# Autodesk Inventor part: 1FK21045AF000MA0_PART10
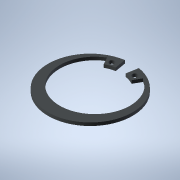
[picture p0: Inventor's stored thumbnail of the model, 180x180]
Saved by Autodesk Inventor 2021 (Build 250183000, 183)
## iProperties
Created: 2025-04
Part Number: 1FK21045AF000MA0_PART10
Material: Generic
Catalog Web Link: www.3dfindit.com
Description: -Servo synchronous motor
Document SubType Name: Modeling
Designer: psAdmin
Mass: 0.642463 g
Surface Area: 12.3927 cm^2
Volume: 0.642463 cm^3
Density: 1 g/cm^3
Appearance: PSOLRGB-212-217-219
Category: PARTsolutions
Title: 1FK21045AF000MA0_PART10
Author: Cadenas PARTsolutions
Comments: Servo synchronous motor
Sending System: PARTsolutions
Preprocessor: ST-DEVELOPER v19.3
PSOL_IDENT_0: {$CADENAS_DATA/23d-libs/siemens_ag/_cat_/8b/0a/1fk21045af000ma0.prj},216 {VTYP=3D},{NB=1FK21045AF000
PSOL_IDENT_1: MA0_PART10},{LINA=1FK21045AF000MA0_PART10},{NN=1FK21045AF000MA0_PART10},{NOPRJ=TRUE},{DATE=19.08.202
PSOL_IDENT_2: 5 14:00:48},{GEOMDATE=30.07.2025 02:00:28},{VERSION=},{LINEID=10},{WBVAR=},{WBNUMERIC=}  {NB=1FK2104
PSOL_IDENT_3: 5AF000MA0_PART10},{LINA=1FK21045AF000MA0_PART10},{KT=DUMMY},{PREVIEW=../../../_pool_/a9/69/p_d211_xx
PSOL_IDENT_4: _00818j.png},{DESCSHORT=SIMOTICS S-1FK2 HD, SINAMICS S210 3AC 400V-480V, 2.4 Nm, 3000 rpm},{DESCLONG=
PSOL_IDENT_5: SIMOTICS S-1FK2 HD servo motor M0=2.4 Nm; PN = 0.75 kW at nN=3000 rpm (380-480 V); PN = 0.375 kW at
PSOL_IDENT_6: nN=1500 rpm (200-240 V); degree of protection IP64; cylindrical shaft D19x40mm; absolute encoder 22-
PSOL_IDENT_7: bit + 12-bit multiturn (encoder AM22DQC); with OCC interface; plug size M17, rotatable; SIMOTICS S-1
PSOL_IDENT_8: FK2 servomotorfor a wide range of uses in industrial environments. SIMOTICS S‑1FK2 servomotors are c
PSOL_IDENT_9: ompact synchronous motors with a high dynamic performance that set themselves apart as a result of t
PSOL_IDENT_10: heir high power density, degree of protection and overload capability. The motors are available in t
PSOL_IDENT_11: wo variants: as High Dynamic variant (highest dynamic performance as a result of the low intrinsic m
PSOL_IDENT_12: oment of inertia for applications demanding a high dynamic performance with low moved masses) - and
PSOL_IDENT_13: as Compact variant (precise and stable closed-loop control for medium up to large moved masses as a
PSOL_IDENT_14: result of a medium intrinsic moment of inertia). SIMOTICSS‑1FK2 servomotors fully exploit their stre
PSOL_IDENT_15: ngths in a system with the SINAMICSS210 frequency converter and simple connection using the one cabl
PSOL_IDENT_16: e connection (OCC). Advantages include the short control and positioning times, fast and precise cor
PSOL_IDENT_17: rection of disturbing quantities as well as stable control with a high dynamic performance. The serv
PSOL_IDENT_18: o motors can be configured to address a wide range of requirements. For example with and without hol
PSOL_IDENT_19: ding brake, IP64 or IP65 degree of protection, singleturn or multiturn absolute encoders - to name j
PSOL_IDENT_20: ust a few. Further, the servomotors are available in different shaft heights extending from 20 to 10
PSOL_IDENT_21: 0. A shaft sealing ring is available to achieve an IP65 degree of protection and for subsequent moun
PSOL_IDENT_22: ting at the motor or as spare part. SIMOTICS - the optimum motor for each and every motion control a
PSOL_IDENT_23: pplication.},{INTNO=195125050112},{SUPPLIERALTNO=1FK2104-5AF00-0MA0},{MANUID=1FK21045AF000MA0},{MANU
PSOL_IDENT_24: NAME=Siemens},{MANUTYPEDESC=Synchronous motor 1FK2-HD 2.4 NM},{AAU732=SIMOTICS},{AAO057=S-1FK2},{AAU
PSOL_IDENT_25: 734=SIMOTICS S-1FK2 HD servo motor M0=2.4 Nm; PN = 0.75 kW at nN=3000 rpm (380-480 V); PN = 0.375 kW
PSOL_IDENT_26: at nN=1500 rpm (200-240 V); degree of protection IP64; cylindrical shaft D19x40mm; absolute encoder
PSOL_IDENT_27: 22-bit + 12-bit multiturn (encoder AM22DQC); with OCC interface; plug size M17, rotatable;},{AAW338=
PSOL_IDENT_28: Synchronous motor 1FK2-HD 2.4 NM},{AAO742=SIMOTICS},{AAO663=4042948692912},{NOCUPEROU=1},{PRICEQUANT
PSOL_IDENT_29: ITY=1},{QUANTITYMIN=1},{QUANTITYINT=1},{CTN=85015100},{COO=DE},{AAO676=1FK2104-5AF00-0MA0},{AAO677=S
PSOL_IDENT_30: iemens AG},{ORDERUNIT=C62},{CONTENTUNIT=C62}
NB: 1FK21045AF000MA0_PART10
NT: Servo synchronous motor
NBSYN: $MANUID._PART10
LINA: 1FK21045AF000MA0_PART10
CATALOG: SIEMENS
PREVIEW: ../../../_pool_/a9/69/p_d211_xx_00818j.png
DESCSHORT: SIMOTICS S-1FK2 HD, SINAMICS S210 3AC 400V-480V, 2.4 Nm, 3000 rpm
DESCLONG: SIMOTICS S-1FK2 HD servo motor M0=2.4 Nm; PN = 0.75 kW at nN=3000 rpm (380-480 V); PN = 0.375 kW at nN=1500 rpm (200-240 V); degree of protection IP64; cylindri
INTNO: 195125050112
SUPPLIERALTNO: 1FK2104-5AF00-0MA0
MANUID: 1FK21045AF000MA0
MANUNAME: Siemens
MANUTYPEDESC: Synchronous motor 1FK2-HD 2.4 NM
AAU732: SIMOTICS
AAO057: S-1FK2
AAU734: SIMOTICS S-1FK2 HD servo motor M0=2.4 Nm; PN = 0.75 kW at nN=3000 rpm (380-480 V); PN = 0.375 kW at nN=1500 rpm (200-240 V); degree of protection IP64; cylindri
AAW338: Synchronous motor 1FK2-HD 2.4 NM
AAO742: SIMOTICS
AAO663: 4042948692912.0
NOCUPEROU: 1
PRICEQUANTITY: 1
QUANTITYMIN: 1
QUANTITYINT: 1
CTN: 85015100
COO: DE
ARTICLENO: 1FK21045AF000MA0_PART10
BOMINFO: 1FK21045AF000MA0_PART10
CREATOR: CADENAS GmbH
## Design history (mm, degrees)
feature "2025_04_17_15_40_42_0766"
body "Solid1"
